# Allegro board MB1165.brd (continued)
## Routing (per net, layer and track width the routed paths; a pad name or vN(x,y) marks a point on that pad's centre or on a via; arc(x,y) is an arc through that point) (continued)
PAR_D4: length 149.9
  TOP w0.127: CN4.27 150.06,143.69 v1(150.47,143.28) ; U4.B13 83.61,132.89 87.08,132.89 87.5,132.46 87.5,131.57 89.53,129.54 93.09,129.54 94.57,128.06 94.57,124.12 95.76,122.94 CN6.53 111.12,122.94 111.46,123.27 v1(111.89,123.27)
  L3_SIG w0.102: v1(150.47,143.28) 150.47,143.94 151,144.47 151,145.29 150.68,145.62 149.61,145.62 148.99,146.23 148.99,156.55 147.22,158.32 126.29,158.32 125.48,159.13 103.76,159.13 102.88,158.25 102.35,158.25 101.07,156.97 98.04,156.97 v1(97.84,157.18)
  BOTTOM w0.127: R272.2 111.56,122.94 v1(111.89,123.27) 112.37,123.75 112.37,125.35 111.1,126.62 107.75,126.62 106.96,127.41 106.96,132.77 104.42,135.31 104.42,152.3 100.63,156.08 99.95,156.08 98.86,157.18 v1(97.84,157.18)
PAR_D5: length 92.8
  TOP w0.127: v1(150.5,142.42) 151.17,143.09 151.4,143.09 152,143.69 CN4.28 ; v1(111.86,143.26) 111.86,142.75 111.1,141.99 CN6.23 ; v5(82.81,134.49) U4.C11
  L3_SIG w0.102: v1(150.5,142.42) 148.69,142.42 145.41,145.69 145.41,152.98 143.21,155.19 135.13,155.19 129.67,149.73 120.9,149.73 113.94,142.77 113.27,142.77 112.78,143.26 v1(111.86,143.26) 110.74,143.26 108.69,141.2 98.2,141.2 92.38,135.38 88.16,135.38 87.15,136.4 86.06,136.4 84.68,135.03 83.35,135.03 v5(82.81,134.49)
PAR_D6: length 76.1
  TOP w0.127: CN4.29 148.75,142.69 147.45,143.99 147.45,146.61 147.19,146.86 v1(147.19,147.19) ; SB4.1 91.64,149.81 91.64,150.04 93.8,152.2 93.8,155.04 v1(93.85,155.09)
  L3_SIG w0.102: v1(147.19,147.19) 147.57,147.57 147.57,150.81 147,151.38 147,154.37 144.4,156.97 126.36,156.97 125.48,156.08 123.57,156.08 122.61,157.05 111.33,157.05 109.17,154.89 94.06,154.89 v1(93.85,155.09)
PAR_D7: length 58.6
  TOP w0.127: CN4.30 154.43,142.69 154.71,142.98 v1(155.63,142.98) ; SB17.1 v1(131.32,104.65)
  L3_SIG w0.102: v1(155.63,142.98) 155.93,142.67 155.93,121.89 150.9,116.87 146.69,116.87 143.13,113.31 141.33,113.31 136.22,108.2 133.96,108.2 131.32,105.56 v1(131.32,104.65)
PAR_D8: length 245.3
  TOP w0.127: R17.2 28.07,157.35 v1(29.72,157.35) ; U4.B14 83.64,132.06 86.45,132.06 89.35,129.16 92.71,129.16 94,127.87 94,123.82 96.16,121.67 CN6.55 111.07,121.67 111.58,122.17 v1(111.86,122.17) ; v1(150.62,153.01) 150.31,152.69 CN4.9
  L3_SIG w0.102: v1(29.72,157.35) 32.89,157.35 35.31,159.77 38.58,159.77 39.52,158.83 43.1,158.83 44.04,159.77 58.55,159.77 59.82,161.04 66.04,161.04 66.8,161.8 81.66,161.8 83.19,160.27 94.11,160.27 96.16,158.22 97.56,158.22 98.55,157.23 100.84,157.23 102.36,158.75 102.74,158.75 103.63,159.64 106.68,159.64 107.82,160.78 119,160.78 120.02,159.77 126.11,159.77 126.87,159 147.57,159 149.73,156.84 149.73,153.9 v1(150.62,153.01) 151.05,152.58 151.05,152.07 149.99,151 149.99,146.69 150.24,146.43 150.93,146.43 152.3,145.06 152.3,140.03 150.64,138.38 142.16,138.38 141.58,138.96 128.27,138.96 116.23,126.92 116.23,122.48 113.89,120.14 v1(113.89,118.24)
  BOTTOM w0.127: v1(113.89,118.24) 113.89,120.27 111.99,122.17 v1(111.86,122.17) 111.23,121.54 111.23,121.39 R278.2
PAR_D9: length 239.3
  TOP w0.127: v5(86.76,133.35) 86.74,133.35 86.36,133.73 84.37,133.73 U4.A12 ; CN17.5 v1(140.52,48.57) ; v1(154.94,152.69) CN4.10 ; CN6.28 113.61,139.45 v1(113.51,139.55)
  L3_SIG w0.102: v1(102.87,160.78) 106.43,160.78 107.31,161.67 126.62,161.67 127.81,160.48 147.75,160.48 149.48,158.75 150.75,158.75 152.15,157.35 152.15,156.08 154.47,153.76 154.47,153.17 v1(154.94,152.69) 155.96,151.68 155.96,149.39 156.24,149.11 156.24,121.59 151.08,116.43 146.69,116.43 143.21,112.95 141.43,112.95 139.95,111.48 139.95,102.87 142.24,100.58 142.24,50.29 v1(140.52,48.57) ; v5(86.76,133.35) 86.89,133.22 94.59,133.22 98.83,137.46 106.68,137.46 107.89,138.67 112.66,138.67 113.51,139.52 v1(113.51,139.55)
  BOTTOM w0.127: v1(113.51,139.55) 113.44,139.62 112.75,139.62 109.65,142.72 109.65,154.38 107.31,156.72 107.31,158.37 104.9,160.78 v1(102.87,160.78)
PAR_D10: length 115.8
  TOP w0.102: v5(83.61,134.49) 83.62,134.49 84.45,134.49 84.84,134.11 85.09,134.11
  TOP w0.127: v5(83.61,134.49) U4.B11 ; 85.09,134.11 86.61,134.11 87.88,132.84 87.88,131.7 89.66,129.92 93.47,129.92 98.93,124.46 JP6.2 101.5,126.77 v1(106.91,126.77) 109.97,126.77 CN6.47 ; v1(147.32,155.32) 147.95,154.69 CN4.5
  L3_SIG w0.102: v1(147.32,155.32) 145.34,157.3 125.93,157.3 125.22,156.59 124.08,156.59 123.32,157.35 111.12,157.35 108.99,155.22 100.86,155.22 v1(100.51,155.57)
  BOTTOM w0.127: v1(100.51,155.57) 100.69,155.57 104.06,152.2 104.06,135.2 106.71,132.56 106.71,126.97 v1(106.91,126.77)
PAR_D11: length 107.9
  TOP w0.127: v1(111.84,120.7) 111.53,120.4 CN6.57 96.49,120.4 93.47,123.42 93.47,127.64 92.33,128.78 89.15,128.78 86.36,131.57 v1(85.47,131.57) ; CN4.6 151.98,154.69 151.38,154.1 151.38,153.09 v1(150.62,152.32) ; v5(82.01,133.69) U4.D12
  L3_SIG w0.102: v1(85.47,131.57) 85.09,131.95 84.45,131.95 83.17,133.24 82.45,133.24 v5(82.01,133.69) ; v1(150.62,152.32) 149.73,151.43 149.73,146.43 149.99,146.18 150.83,146.18 152.02,144.98 152.02,140.72 151.51,140.21 146.49,140.21 145.67,139.4 128.14,139.4 115.77,127.03 115.77,122.68 113.94,120.85 112.01,120.85 111.86,120.7 v1(111.84,120.7)
  BOTTOM w0.127: SB83.2 111.56,120.4 111.56,120.42 v1(111.84,120.7)
PB0: length 37.2
  TOP w0.127: CN5.52 48.01,124.21 48.64,124.84 v1(48.77,124.84) 49.97,126.05 49.97,129.35 58.8,138.18 68.2,138.18 69.71,139.69 U4.R5
  BOTTOM w0.127: SB76.2 SB79.2 48.26,124.33 v1(48.77,124.84)
PB1: length 29.5
  TOP w0.127: U4.R4 68.35,140.49 67.44,139.57 65.91,139.57 64.77,140.72 v1(48.77,140.72) CN5.26
  BOTTOM w0.127: SB50.2 48.26,141.22 v1(48.77,140.72) ; SB51.2 47.62,140.97
PB2: length 81.9
  TOP w0.127: v1(43.43,138.3) 43.31,138.18 CN5.29 40.51,138.18 36.78,141.91 31.19,141.91 29.97,143.13 29.97,154.43 32.51,156.97 36.7,156.97 37.85,158.12 41.53,158.12 43.94,160.53 R6.2 ; U4.M5 v5(74.81,140.09)
  L3_SIG w0.102: v5(74.81,140.09) 74.81,139.83 74.42,139.45 74.42,139.2 74.16,138.93 73.95,138.93 73.53,138.51 73.53,138.05 72.26,136.78 71.12,136.78 70.42,136.08 67.75,136.08 66.67,135 56.64,135 54.48,137.16 49.78,137.16 49.28,137.67 44.2,137.67 43.56,138.3 v1(43.43,138.3)
PB3: length 31.7
  TOP w0.127: U4.A10 84.06,135.64 85.57,135.64 86.33,134.87 87.09,134.87 87.59,134.38 87.59,133.77 88.26,133.1 88.26,131.83 89.79,130.3 93.85,130.3 95.89,128.27 97.92,128.27 JP5.2 101.22,127.51 108.33,127.51 108.84,128.02 CN6.45
PB4: length 217.7
  TOP w0.102: 85.09,136.45 84.05,136.45 U4.A9
  TOP w0.127: v5(87.06,135.85) 86.47,136.45 85.09,136.45 ; v1(123.06,102.23) 123.19,102.11 124.84,102.11 R103.2 ; CN6.24 v1(113.54,141.99) ; v1(44.07,34.42) 44.07,34.29 43.68,33.9 U21.19
  L3_SIG w0.102: v1(44.07,34.42) 44.96,35.31 48.26,35.31 49.15,36.2 49.15,38.51 51.71,41.07 56.64,41.07 60.48,44.91 80.21,44.91 81.41,46.1 81.41,47.09 82.96,48.64 83.87,48.64 101.17,65.94 101.17,69.34 102.54,70.71 105.54,70.71 107.87,73.05 107.87,74.88 110.72,77.72 110.72,87.66 117.22,94.16 117.22,95.38 120.98,99.14 122.81,99.14 123.77,100.1 123.77,101.52 v1(123.06,102.23) ; v5(87.06,135.85) 87.08,135.85 87.93,135 92.58,135 98.4,140.82 108.94,140.82 110.74,142.62 112.9,142.62 v1(113.54,141.99) 125.09,141.99 v1(125.86,142.75)
  BOTTOM w0.127: v1(125.86,142.75) 126.62,141.99 126.62,116.46 121.67,111.51 121.67,103.63 v1(123.06,102.23)
PB5: length 55
  TOP w0.127: v1(44.7,153.03) 45.02,153.35 45.02,153.97 45.73,154.69 CN5.4 ; v5(84.56,137.21) 84.48,137.29 U4.A8
  L3_SIG w0.102: v5(84.56,137.21) 83.29,137.69 79.88,137.69 78.49,139.09 78.49,140.67 77.62,141.53 77.62,141.78 77.36,142.04 77.09,142.04 76.78,142.35 76.78,142.67 70.87,148.59 67.67,148.59 63.75,152.5 52.07,152.5 51.41,153.16 44.83,153.16 v1(44.7,153.03)
  BOTTOM w0.127: SB28.2 SB29.2 45.59,153.92 v1(44.7,153.03)
PB6: length 155
  TOP w0.127: v1(91.69,136.88) 91.34,136.53 R40.2 ; v1(33.66,151.51) U3.7 ; v1(113.54,145.8) CN6.18 116.59,145.8 119,148.21 119,158.62 v1(121.03,160.66)
  L3_SIG w0.102: v1(91.69,136.88) 98.48,143.66 108.1,143.66 110.87,146.43 112.9,146.43 v1(113.54,145.8)
  BOTTOM w0.127: v1(33.66,151.51) R215.2 35.43,152.02 35.43,158.24 39.88,162.69 39.88,168.28 42.27,170.66 111.02,170.66 v1(121.03,160.66)
PB7: length 94.9
  TOP w0.127: CN4.32 151.78,141.69 151.38,142.09 v1(151.05,142.09) ; v5(88.01,137.44) 87.99,137.44 87.22,138.2 87.22,139.09 86.49,139.83 84.43,139.83 84.2,140.06 83.58,140.06 U4.B5 ; CN6.21 111.05,143.26 111.56,143.76 112.27,143.76 112.67,144.17 v1(112.67,145.8)
  L3_SIG w0.102: v1(151.05,142.09) 151.05,142.54 150.75,142.85 148.87,142.85 145.75,145.97 145.75,153.21 143.26,155.7 135.13,155.7 129.67,150.24 119.89,150.24 114.81,145.16 113.54,145.16 112.9,145.8 v1(112.67,145.8) 111,145.8 108.41,143.21 98.63,143.21 92.56,137.13 91.82,136.4 89.71,136.4 89.1,137.01 88.44,137.01 v5(88.01,137.44)
PB8: length 452.5
  TOP w0.127: CN6.31 108.56,136.91 v1(107.77,136.12) 104.88,133.22 89.11,133.22 88.27,134.07 88.27,134.52 87.78,135 87.78,136.19 86.87,137.11 85.27,137.11 84.29,138.09 U4.A7 ; R5.1 40.64,161.54 v1(40.39,161.29) ; CN18.40 69.53,38.65 v1(69.47,38.59) 69.34,38.46 R151.2 ; CN15.44 100.32,80.38 99.44,79.5 99.44,78.11 100.46,77.09 100.46,75.18 101.22,74.42 101.22,70.05 v1(102.34,68.94) ; v1(125.09,23.34) 124.69,23.34 R179.1
  L3_SIG w0.102: v1(40.39,161.29) 40.89,161.8 62.06,161.8 62.3,161.56 62.66,161.56 62.9,161.8 66.17,161.8 66.55,162.18 81.92,162.18 83.44,160.66 94.36,160.66 96.39,158.62 97.66,158.62 98.81,157.48 100.46,157.48 102.49,159.51 v1(102.74,159.51) 103,159.51 103.5,160.02 106.3,160.02 107.57,161.29 126.24,161.29 127.64,159.89 147.83,159.89 150.62,157.1 150.62,155.7 151.05,155.27 v1(151.05,154.46) 152.91,152.6 152.91,149.48 154.36,148.03 154.36,145.72 153.77,145.14 153.77,135.92 155.57,134.11 155.57,122.12 150.75,117.3 146.56,117.3 142.93,113.67 141.22,113.67 136.14,108.58 133.91,108.58 130.78,105.46 130.78,101.45 126.75,97.41 125.86,97.41 117.4,88.95 117.4,79.4 112.33,74.33 112.33,71.06 111.06,69.79 109.69,69.79 v1(109.37,69.47) 79.27,39.37 70.25,39.37 v1(69.47,38.59) 64.5,38.59 63.67,37.76 56.94,37.76 54.99,35.81 v1(54.99,35.69)
  BOTTOM w0.127: v1(102.74,159.51) 103.76,159.51 105.03,158.24 105.03,156.97 107.75,154.25 107.75,136.14 v1(107.77,136.12) ; v1(102.34,68.94) 108.84,68.94 v1(109.37,69.47) ; v1(69.47,38.59) 74.79,33.27 101.6,33.27 111.51,23.37 125.07,23.37 v1(125.09,23.34) ; v1(151.05,154.46) 151.38,154.46 151.74,154.81 T5.3 152.53,154.35 R295.1 ; R287.1 55.5,35.18 v1(54.99,35.69)
PB9: length 539
  TOP w0.127: v1(102.34,69.7) 101.73,70.31 101.73,74.68 100.84,75.56 100.84,77.47 99.95,78.36 99.95,79.25 101.32,80.62 CN15.40 ; v1(113.54,148.34) CN6.14 116.97,148.34 118.49,149.86 118.49,158.88 v1(120.27,160.66) ; CN18.38 v1(70.8,38.61) 70.8,37.71 R152.2 ; R4.1 v1(40.64,167.39) ; R172.1 127.51,26.67 v1(125.98,26.67) ; U4.B4 83.61,140.89 84.79,140.89 85.23,140.45 86.25,140.45 v5(86.49,140.68)
  L3_SIG w0.102: v1(102.34,69.7) 102.84,70.21 105.66,70.21 108.18,72.72 108.18,74.7 111.05,77.57 111.05,87.48 117.6,94.03 117.6,95.33 120.88,98.6 122.71,98.6 125.91,101.8 127.25,101.8 127.51,102.06 127.51,103.33 126.03,104.8 126.03,110.82 126.72,111.51 130.91,111.51 131.44,112.04 131.44,112.93 133.6,115.09 138.66,115.09 140.34,116.76 141.96,116.76 145.47,120.27 149.71,120.27 150.19,120.75 150.19,127.56 150.98,128.35 152.83,128.35 153.75,129.26 153.75,133.63 152.58,134.8 152.58,145.41 151.31,146.69 150.62,146.69 150.24,147.07 150.24,150.88 151.51,152.15 151.51,153.03 150.55,154 v1(150.55,154.91) 150.24,155.22 150.24,156.84 147.7,159.38 127.13,159.38 126.36,160.15 120.78,160.15 v1(120.27,160.66) ; v1(113.54,148.34) 112.9,148.97 110.74,148.97 109.22,147.45 95.76,147.45 92.2,143.89 90.83,143.89 89.28,142.34 88.14,142.34 v5(86.49,140.68) ; v1(118.31,73.71) 118.31,70.54 115.52,67.74 115.52,37.85 116.1,37.26 116.1,33.43 118.41,31.11 118.41,30.71 118.24,30.53 118.24,29.79 119.05,28.98 122.12,28.98 124.43,26.67 v1(125.98,26.67) ; v1(70.8,38.61) 70.17,37.97 64.52,37.97 64.01,37.47 57.38,37.47 v1(55.63,35.71)
  BOTTOM w0.127: v1(120.27,160.66) 110.74,170.18 43.43,170.18 v1(40.64,167.39) ; R288.1 56.13,34.04 56.13,35.18 55.63,35.69 v1(55.63,35.71) ; v1(118.31,73.71) 119.05,74.45 119.05,84.53 117.47,86.11 117.47,96.39 116.84,97.03 116.84,111.73 123.7,118.59 123.7,130.81 122.92,131.58 122.92,138.44 117.08,144.28 117.08,145.02 113.77,148.34 v1(113.54,148.34) ; v1(150.55,154.91) 150.32,154.69 T6.3 148.12,152.36 R296.1 ; v1(70.8,38.61) 71.81,38.61 76.63,33.78 101.98,33.78 111.89,23.88 122.1,23.88 124.89,26.67 v1(125.98,26.67)
PB10: length 110.2
  TOP w0.127: v1(43.36,135.56) 43.28,135.64 CN5.33 ; R94.2 v1(34.8,107.57) ; v5(73.21,133.69) U4.P12
  L3_SIG w0.102: v1(34.8,107.57) 34.8,107.65 39.22,112.06 39.22,125.65 38.73,126.14 38.73,129.84 38.86,129.97 39.9,129.97 40.03,130.1 40.03,132.54 40.16,132.66 42.37,132.66 42.47,132.76 42.47,132.97 42.37,133.07 39.39,133.07 39.27,133.19 39.27,133.36 39.39,133.47 42.37,133.47 42.47,133.58 42.47,133.78 42.37,133.88 39.45,133.88 39.32,134.01 39.32,134.21 39.45,134.34 42.29,134.34 42.42,134.47 42.42,134.62 42.29,134.74 39.4,134.74 39.27,134.87 39.27,135.02 39.4,135.15 42.34,135.15 42.47,135.28 42.47,135.43 42.34,135.56 39.34,135.56 39.22,135.68 39.22,135.88 39.34,136 42.37,136 42.49,136.13 42.49,136.28 42.37,136.41 39.34,136.41 39.22,136.54 39.22,136.69 39.34,136.82 42.34,136.82 42.47,136.94 42.47,137.1 42.34,137.22 39.34,137.22 39.22,137.35 39.22,137.54 39.34,137.67 42.47,137.67 43,137.13 43,135.92 v1(43.36,135.56) 48.18,135.56 48.59,135.15 53.77,135.15 55.83,133.1 67.16,133.1 68.35,134.29 72.64,134.29 73.21,133.72 v5(73.21,133.69)
PB11: length 110
  TOP w0.127: v1(44.25,135.03) 45.09,135.03 45.75,134.37 CN5.36 ; v1(34.8,106.17) 35.43,105.54 R98.2 ; v5(72.41,132.89) U4.R13
  L3_SIG w0.102: v1(34.8,106.17) 34.8,105.46 34.92,105.33 35.18,105.33 35.31,105.46 35.31,107.64 39.57,111.91 39.57,126.31 39.09,126.8 39.09,129.57 39.22,129.69 40.28,129.69 40.41,129.82 40.41,131.29 40.51,131.4 43.06,131.4 43.18,131.52 43.18,131.68 43.06,131.8 40.51,131.8 40.41,131.9 40.41,132.16 40.54,132.28 42.57,132.28 42.75,132.46 42.75,134.85 42.93,135.03 v1(44.25,135.03) 44.37,135.15 45.7,135.15 45.82,135.03 45.82,134.49 45.93,134.37 46.1,134.37 46.22,134.49 46.22,135.06 46.34,135.18 46.51,135.18 46.63,135.06 46.63,134.51 46.75,134.39 46.92,134.39 47.03,134.51 47.03,135.03 47.15,135.15 47.32,135.15 47.44,135.03 47.44,134.51 47.56,134.39 47.73,134.39 47.85,134.51 47.85,134.96 47.97,135.08 48.13,135.08 48.25,134.96 48.25,134.49 48.37,134.37 48.54,134.37 48.66,134.49 48.66,134.65 48.76,134.75 48.96,134.75 49.07,134.65 49.07,134.13 49.19,134.01 49.35,134.01 49.47,134.13 49.47,134.65 49.57,134.75 49.78,134.75 49.88,134.65 49.88,133.39 50,133.27 50.17,133.27 50.29,133.39 50.29,134.65 50.39,134.75 50.59,134.75 50.69,134.65 50.69,132.76 50.81,132.64 50.98,132.64 51.1,132.76 51.1,134.65 51.2,134.75 51.4,134.75 51.5,134.65 51.5,132.64 51.63,132.51 51.84,132.51 51.97,132.64 51.97,134.62 52.1,134.75 52.3,134.75 52.43,134.62 52.43,132.56 52.55,132.44 52.79,132.44 52.92,132.56 52.92,134.57 53.05,134.7 53.26,134.7 53.39,134.57 53.39,132.41 53.52,132.28 68.12,132.28 68.25,132.41 68.25,133.73 68.38,133.86 68.61,133.86 68.71,133.76 68.71,132.72 68.81,132.61 69.01,132.61 69.11,132.72 69.11,133.76 69.22,133.86 69.42,133.86 69.52,133.76 69.52,132.72 69.62,132.61 69.82,132.61 69.93,132.72 69.93,133.76 70.03,133.86 70.23,133.86 70.33,133.76 70.33,132.72 70.43,132.61 70.64,132.61 70.74,132.72 70.74,133.76 70.84,133.86 71.04,133.86 71.15,133.76 71.15,132.72 71.25,132.61 71.45,132.61 71.55,132.72 71.55,133.76 71.65,133.86 72.28,133.86 72.41,133.73 v5(72.41,132.89)
PB12: length 48.6
  TOP w0.127: U4.L13 76.38,132.92 v5(76.43,132.92) ; CN5.41 43.15,130.56 v1(43.41,130.3)
  L3_SIG w0.102: v5(76.43,132.92) 76.38,132.92 74.87,131.41 74.87,129.86 71.25,126.24 65.34,126.24 62.5,129.08 49.07,129.08 48.36,129.79 44.83,129.79 44.32,130.3 v1(43.41,130.3)
  BOTTOM w0.127: R254.2 44.96,127.51 44.45,128.02 44.45,129.67 44.07,130.05 43.66,130.05 v1(43.41,130.3) 43.28,130.43 SB70.2 SB74.2
PB13: length 110.5
  TOP w0.127: v1(43.56,128.27) 42.55,129.29 CN5.43 ; U4.K14 76.41,132.09 v5(76.34,132.09) ; R109.2 v1(34.67,102.87)
  L3_SIG w0.102: v1(34.67,102.87) 34.67,103.12 34.8,103.25 36.07,103.25 36.2,103.38 36.2,107.34 40.41,111.56 40.41,116.71 40.54,116.84 42.09,116.84 42.24,116.99 42.24,124.66 42.82,125.25 42.82,126.64 42.72,126.75 41.38,126.75 41.25,126.87 41.25,127.08 41.38,127.2 43,127.2 43.13,127.33 43.13,127.51 43,127.64 41.39,127.64 41.27,127.75 41.27,127.92 41.39,128.04 42.83,128.04 42.95,128.16 42.95,128.33 42.83,128.45 41.35,128.45 41.25,128.55 41.25,128.75 41.35,128.85 42.67,128.85 42.77,128.96 42.77,129.16 42.67,129.26 41.38,129.26 41.25,129.39 41.25,129.59 41.38,129.72 43.28,129.72 43.41,129.59 43.41,128.42 v1(43.56,128.27) 43.81,128.27 43.92,128.37 43.92,129.44 44.04,129.57 44.22,129.57 44.35,129.44 44.35,127.61 44.5,127.46 45.65,127.46 45.77,127.58 45.77,128.74 45.89,128.85 46.06,128.85 46.18,128.74 46.18,126.79 46.3,126.67 46.47,126.67 46.59,126.79 46.59,128.74 46.7,128.85 46.87,128.85 46.99,128.74 46.99,126.76 47.11,126.64 47.28,126.64 47.4,126.76 47.4,128.71 47.52,128.83 47.69,128.83 47.8,128.71 47.8,126.74 47.92,126.62 48.09,126.62 48.21,126.74 48.21,128.68 48.34,128.8 48.56,128.8 48.69,128.68 48.69,126.77 48.82,126.64 49.02,126.64 49.15,126.77 49.15,127.97 49.28,128.09 49.5,128.09 49.63,127.97 49.63,126.77 49.76,126.64 63.86,126.64 65.02,125.48 71.5,125.48 75.39,129.37 75.39,131.14 v5(76.34,132.09)
  BOTTOM w0.127: R255.2 42.8,127.51 v1(43.56,128.27)
PB14: length 38.9
  TOP w0.127: CN5.35 43.56,134.37 43.79,134.14 v1(43.79,133.91) ; v5(72.41,132.09) U4.R14
  L3_SIG w0.13: v1(43.79,133.91) 43.79,134.09 44.15,134.44 44.94,134.44 46.26,133.12 49.12,133.12 50.67,131.57 69.39,131.57 69.7,131.88 72.2,131.88 v5(72.41,132.09)
  BOTTOM w0.127: SB65.2 SB64.2
  BOTTOM w0.155: v1(43.79,133.91) 43.79,134.11 43.28,134.62 41.02,134.62 40.89,134.49 40.89,134.11
PB15: length 38.7
  TOP w0.127: v1(44.45,133.91) 45.26,133.1 CN5.38 ; v5(72.41,131.29) U4.R15
  L3_SIG w0.13: v1(44.45,133.91) 44.45,133.93 44.58,134.06 44.78,134.06 46.1,132.74 48.97,132.74 50.52,131.19 69.55,131.19 69.86,131.5 72.2,131.5 v5(72.41,131.29)
  BOTTOM w0.127: SB61.2 SB62.2
  BOTTOM w0.155: v1(44.45,133.91) 44.45,133.99 43.43,135 41.02,135 40.89,135.13 40.89,135.51
PC0: length 56.4
  TOP w0.127: v1(36.32,141.22) 35.84,140.74 32.66,140.74 JP3.3 ; v5(74.81,142.49) U4.M2 ; CN5.11 42.55,149.61 43.05,150.11 v1(43.43,150.11)
  L3_SIG w0.102: v1(36.32,141.22) 36.5,141.4 36.5,143.81 39.75,147.07 39.75,148.87 41,150.11 v1(43.43,150.11) 44.09,150.11 44.88,149.33 50.52,149.33 51.83,148.02 56.43,148.02 57.81,146.63 63.42,146.63 64.52,145.54 66.8,145.54 67.59,144.75 68.86,144.75 69.42,144.2 72.82,144.2 73.65,143.36 73.65,143.14 73.92,142.88 74.42,142.88 v5(74.81,142.49)
  BOTTOM w0.127: v1(43.43,150.11) 42.93,150.62 SB34.1
PC1: length 43.3
  TOP w0.127: v1(44.7,151.89) 43.94,151.13 43.94,147.96 v1(44.83,147.07) CN5.16 ; U4.M3 v5(74.81,141.69)
  L3_SIG w0.102: v1(44.83,147.07) 45.34,147.07 46.15,146.25 49.45,146.25 51.74,143.97 59.74,143.97 60.71,143 64.64,143 65.53,142.11 74.38,142.11 v5(74.81,141.69)
  BOTTOM w0.127: SB41.1 45.34,147.57 v1(44.83,147.07) ; v1(44.7,151.89) 45.09,152.27 SB31.1
PC2: length 41.6
  TOP w0.127: CN5.23 v1(43.41,141.99) ; U4.M4 v5(74.81,140.89)
  L3_SIG w0.102: v5(74.81,140.89) 74.39,140.46 73.15,140.46 72.19,139.5 70.66,139.5 69.34,138.18 58.8,138.18 56.39,140.59 49.91,140.59 48.95,141.55 43.84,141.55 v1(43.41,141.99)
  BOTTOM w0.127: v1(43.41,141.99) 43.28,142.11 41.4,142.11 SB49.1 R233.1
PC3: length 42
  TOP w0.127: v1(44.32,139.32) 44.2,139.45 CN5.27 ; U4.L4 v5(75.61,140.89)
  L3_SIG w0.102: v5(75.61,140.89) 75.61,140.89 75.18,140.46 74.68,140.46 74.42,140.21 74.42,139.95 74.17,139.7 73.92,139.7 73.65,139.43 73.65,139.19 71.88,137.41 70.87,137.41 70.1,136.65 67.18,136.65 66.42,135.89 58.33,135.89 55.92,138.3 45.85,138.3 44.83,139.32 v1(44.32,139.32)
  BOTTOM w0.127: v1(44.32,139.32) 44.32,139.06 44.7,138.68 45.59,138.68 45.85,138.43 ; 46.1,136.78 SB54.1
PC4: length 41.4
  TOP w0.127: v5(74.01,140.09) U4.N5 ; v1(43.18,140.08) 42.55,140.72 CN5.25
  L3_SIG w0.102: v1(43.18,140.08) 45.34,140.08 45.97,139.45 56.13,139.45 58.67,136.91 66.17,136.91 66.55,137.29 69.72,137.29 71.25,138.81 72.39,138.81 72.85,139.28 72.85,139.43 73.15,139.73 73.65,139.73 v5(74.01,140.09)
  BOTTOM w0.127: SB53.1 39.75,138.3 41.15,138.3 41.91,139.06 SB52.1 v1(43.18,140.08)
PC5: length 36.9
  TOP w0.102: U4.P5 73.19,140.11 71.63,140.11
  TOP w0.127: v1(44.96,128.52) 45.21,128.52 45.72,128.02 CN5.46 47.96,128.02 58.5,138.56 67.94,138.56 69.49,140.11 71.63,140.11
  BOTTOM w0.127: v1(44.96,128.52) 45.59,128.52 SB73.1 SB69.1
PC13: length 209.4
  TOP w0.127: v1(121.16,82.14) 118.52,79.5 108.71,79.5 106.68,77.47 106.68,54.43 102.16,49.91 102.16,36.02 97.21,31.06 89.74,31.06 88.27,29.59 88.27,19.43 R203.2 ; U4.D1 v5(82.01,143.29) ; CN6.6 114.3,153.42 113.46,152.58 v1(113.46,152.53)
  L3_SIG w0.102: v5(82.01,143.29) 82.01,144.34 85.75,148.08 90.17,148.08 91.44,149.35 92.96,149.35 96.16,152.55 109.75,152.55 110.41,151.89 112.62,151.89 113.26,152.53 v1(113.46,152.53)
  BOTTOM w0.127: v1(121.16,82.14) 121.16,86.36 119.89,87.63 119.89,98.42 120.14,98.68 120.14,112.5 125.27,117.63 125.27,132.08 124.59,132.77 124.59,139.7 119.14,145.15 119.14,146.57 113.46,152.25 v1(113.46,152.53)
PC14: length 9.4
  TOP w0.203: R19.2 84.12,148.39 v1(83.44,147.7) 83.31,147.57 82.68,147.57 82.3,147.19 82.3,146.05 80.64,144.4 80.64,143.05 U4.E1
  BOTTOM w0.127: SB35.1 83.95,148.46 83.44,147.96 v1(83.44,147.7)
PC15: length 8.8
  TOP w0.203: U4.F1 80.14,143.01 80.14,144.65 81.66,146.18 81.66,147.07 v1(80.98,147.75) 80.31,148.41 R18.2
  BOTTOM w0.127: v1(80.98,147.75) 80.9,147.75 80.26,148.39 SB36.1
PD4: length 134.1
  TOP w0.102: v4(72.9,105.37) 73.03,105.37 73.57,105.92 75.36,105.92 U9.G2 ; v5(68.71,76.07) 68.33,75.7 68.33,75.12 U16.A2
  TOP w0.127: CN11.28 v3(103.38,100.89) ; v5(82.01,134.49) U4.D11
  L3_SIG w0.102: v3(103.38,100.89) 102.67,101.6 93.45,101.6 93.07,101.98 92.23,101.98 92.13,101.87 92.13,100.94 92.03,100.84 91.83,100.84 91.73,100.94 91.73,101.87 91.63,101.98 82.16,101.98 81.58,101.4 80.09,101.4 77.8,103.68 77.8,104.03 77.57,104.26 77.06,104.78 73.49,104.78 v4(72.9,105.37)
  BOTTOM w0.127: v5(82.01,134.49) 82.05,134.49 82.42,134.11 83.82,134.11 87.88,130.05 87.88,113.41 100.97,100.33 102.82,100.33 v3(103.38,100.89) ; v4(72.9,105.37) 73.46,105.37 73.58,105.5 73.58,105.79 73.46,105.92 73.03,105.92 72.9,106.05 72.9,106.27 73.03,106.4 73.56,106.4 73.69,106.53 73.69,106.76 73.56,106.88 72.54,106.88 72.42,106.76 72.42,105.5 72.29,105.37 71.99,105.37 71.86,105.5 71.86,105.84 71.73,105.97 71.48,105.97 71.35,105.84 71.35,105.5 71.22,105.37 70.92,105.37 65.84,100.28 65.84,83.67 67.06,82.45 67.06,78.62 67.18,78.5 67.72,78.5 67.84,78.37 67.84,78.12 67.72,77.99 67.18,77.99 67.06,77.86 67.06,77.57 67.18,77.44 68.53,77.44 68.66,77.31 68.66,77.06 68.53,76.93 67.18,76.93 67.06,76.8 67.06,76.61 67.18,76.48 68.58,76.48 68.71,76.35 v5(68.71,76.07)
PD5: length 65.6
  TOP w0.127: v5(82.81,135.29) U4.C10 ; R99.2 v3(90.04,103.5) ; CN11.26 v3(103.38,102.16)
  L3_SIG w0.102: v3(90.04,103.5) 96.28,103.5 96.38,103.4 96.38,102.87 96.48,102.77 96.69,102.77 96.79,102.87 96.79,103.4 96.89,103.5 97.09,103.5 97.2,103.4 97.2,102.87 97.3,102.77 97.5,102.77 97.6,102.87 97.6,103.4 97.7,103.5 98.42,103.5 99.06,102.87 103.28,102.87 103.38,102.77 v3(103.38,102.16)
  BOTTOM w0.127: v3(103.38,102.16) 102.79,101.57 101.24,101.57 88.65,114.17 88.65,130.43 87.63,131.44 87.63,132.59 87.32,132.89 86.05,132.89 85.66,133.29 85.66,133.67 84.2,135.13 82.97,135.13 v5(82.81,135.29)
PD7: length 75
  TOP w0.127: v3(78.49,109.47) 78.61,109.6 R85.2 ; v5(87.2,134.21) 87.02,134.21 86.74,134.49 84.96,134.49 84.57,134.89 U4.A11 ; CN11.24 v3(103.38,103.43)
  L3_SIG w0.102: v3(78.49,109.47) 78.11,109.09 78.11,108.2 80.14,106.17 82.3,106.17 84.02,104.44 98.63,104.44 99.06,104.01 102.79,104.01 v3(103.38,103.43)
  BOTTOM w0.127: v5(87.2,134.21) 87.4,134.21 89.47,132.14 89.47,125.67 90.04,125.09 90.04,114.17 101.35,102.87 102.82,102.87 v3(103.38,103.43)
PE0: length 146.2
  TOP w0.102: v5(71.25,71.5) 71.25,74.55 70.26,75.54 U16.A1 ; v5(89.46,70.43) U15.K9
  TOP w0.127: v5(86,138.43) 86,138.46 85.78,138.68 84.71,138.68 84.51,138.89 U4.A6 ; CN11.25 v3(101.98,102.16)
  L3_SIG w0.102: v5(89.46,70.43) 89.46,69.62 89.59,69.49 90.02,69.49 90.14,69.62 90.14,70.89 90.02,71.02 88.82,71.02 88.7,71.15 88.7,71.6 88.57,71.72 88.17,71.72 87.81,72.08 87.81,72.32 87.61,72.52 84.91,72.52 84.7,72.32 84.7,72.13 84.18,71.6 81.13,71.6 v1(80.77,71.25) 76.71,71.25 76.45,71.5 v5(71.25,71.5)
  BOTTOM w0.127: v5(86,138.43) 86.16,138.43 86.36,138.23 86.36,136.4 86.59,136.17 86.59,134.26 88.07,132.78 88.07,131.57 89.09,130.56 89.09,125.29 89.66,124.71 89.66,113.92 101.42,102.16 v3(101.98,102.16) 102.67,102.16 103.25,102.74 103.73,102.74 104.32,102.16 104.32,93.27 102.87,91.82 88.19,91.82 87.38,91.01 87.38,85.5 84.89,83.01 84.89,78.56 85.43,78.02 85.43,76.32 85.43,75.53 85.22,75.32 84.94,75.32 84.81,75.19 84.81,74.93 84.94,74.81 85.55,74.81 85.67,74.68 85.67,74.47 85.55,74.35 84.43,74.35 84.3,74.22 84.3,73.94 84.43,73.81 85.55,73.81 85.67,73.69 85.67,73.43 85.55,73.3 84.56,73.3 84.43,73.18 84.43,71.42 84.31,71.3 84.05,71.3 83.93,71.42 83.93,73.18 83.8,73.3 83.54,73.3 83.42,73.18 83.42,71.42 83.29,71.3 83.04,71.3 82.91,71.42 82.91,73.18 82.78,73.3 82.55,73.3 82.42,73.18 82.42,71.37 82.3,71.25 82.04,71.25 81.92,71.37 81.92,72.42 81.79,72.54 81.54,72.54 81.41,72.42 81.41,71.37 81.28,71.25 v1(80.77,71.25)
PE1: length 153.7
  TOP w0.102: v5(89.46,77.93) U15.K1 ; 67.94,78.23 67.56,77.85 67.56,75.14 U16.B2
  TOP w0.127: CN11.23 v3(101.98,103.43) ; U4.A5 84.19,139.69 84.43,139.45 86.28,139.45 86.79,138.94 86.79,138.18 v5(86.82,138.15) ; v5(68.83,79.12) 67.94,78.23
  L3_SIG w0.102: v5(68.83,79.12) 68.91,79.2 85.17,79.2 v1(85.34,79.38) 85.34,79.35 85.47,79.22 86.46,79.22 86.59,79.1 86.59,78.64 86.69,78.54 86.89,78.54 86.99,78.64 86.99,79.27 87.12,79.4 87.33,79.4 87.45,79.27 87.45,77.52 87.58,77.39 88.11,77.39 88.24,77.52 88.24,79.38 88.37,79.5 89.44,79.5 89.56,79.38 89.56,79.21 89.44,79.1 88.7,79.1 88.57,78.97 88.57,78.79 88.7,78.66 89.46,78.66 89.59,78.54 89.59,78.44 89.46,78.31 89.15,78.31 89.03,78.18 89.03,77.8 88.9,77.67 88.69,77.67 88.57,77.55 88.57,77.39 88.69,77.27 88.98,77.27 89.1,77.15 89.1,76.98 88.98,76.86 88.77,76.86 88.65,76.73 88.65,76.58 88.77,76.45 88.9,76.45 89.03,76.33 89.03,76.17 88.9,76.05 88.67,76.05 88.54,75.92 88.54,75.79 88.67,75.67 89.33,75.67 89.46,75.79 v5(89.46,77.93)
  BOTTOM w0.127: v1(85.34,79.38) 85.34,82.85 85.47,82.97 90.07,82.97 90.2,83.1 90.2,83.35 90.07,83.48 86.61,83.48 86.49,83.61 86.49,83.86 86.61,83.99 90.07,83.99 90.2,84.12 90.2,84.37 90.07,84.5 88.01,84.5 87.88,84.62 87.88,90.86 88.47,91.44 103.25,91.44 104.72,92.91 104.72,96.07 104.85,96.2 105.28,96.2 105.41,96.32 105.41,96.58 105.28,96.7 104.85,96.7 104.72,96.83 104.72,97.08 104.85,97.21 105.28,97.21 105.41,97.34 105.41,97.59 105.28,97.72 104.85,97.72 104.72,97.85 104.72,98.1 104.85,98.23 105.28,98.23 105.41,98.35 105.41,98.61 105.28,98.74 104.85,98.74 104.72,98.86 104.72,99.12 104.85,99.24 105.28,99.24 105.41,99.37 105.41,99.62 105.28,99.75 104.85,99.75 104.72,99.88 104.72,100.13 104.85,100.26 105.28,100.26 105.41,100.39 105.41,100.64 105.28,100.77 104.85,100.77 104.72,100.89 104.72,101.15 104.85,101.28 105.28,101.28 105.41,101.4 105.41,101.66 105.28,101.78 104.85,101.78 104.72,101.91 104.72,102.16 104.85,102.29 105.28,102.29 105.41,102.42 105.41,102.67 105.28,102.8 104.85,102.8 104.72,102.93 104.72,103.38 104.09,104.01 103.12,104.01 102.54,103.43 v3(101.98,103.43) 101.74,103.43 101.46,103.71 101.21,103.71 90.42,114.49 90.42,125.48 89.92,125.98 89.92,132.33 87.55,134.7 87.55,135.97 86.74,136.78 86.74,138.07 v5(86.82,138.15)
PF6: length 51.5
  TOP w0.127: v1(43.31,151.96) 43.29,151.96 43.1,152.15 CN5.7 37.21,152.15 37.08,152.02 37.08,143.38 36.96,143.26 31.62,143.26 31.5,143.38 31.5,146.23 30.78,146.94 v1(30.73,146.94) ; R25.2 65.66,147.83 v1(65.28,148.21)
  L3_SIG w0.102: v1(65.28,148.21) 64.77,148.72 64.77,150.24 63.5,151.51 48.77,151.51 47.73,152.55 44.53,152.55 43.93,151.96 v1(43.31,151.96)
  BOTTOM w0.127: R227.2 31.11,146.56 v1(30.73,146.94)
PF7: length 52.3
  TOP w0.127: v1(65.28,148.97) 65.41,148.84 R23.2 ; v1(30.73,151) 32.51,151 32.64,151.13 32.64,151.51 32.51,151.64 31.37,151.64 31.24,151.76 31.24,152.53 32.51,153.8 34.8,153.8 38.35,157.35 48.26,157.35 50.42,155.19 50.42,152.78 v1(49.91,152.27) 49.78,152.15 CN5.8
  L3_SIG w0.102: v1(65.28,148.97) 65.28,150.37 63.63,152.02 50.16,152.02 v1(49.91,152.27)
  BOTTOM w0.127: v1(30.73,151) 30.48,151.26 R217.1
PF8: length 52.2
  TOP w0.127: v1(43.41,145.8) CN5.17 38.99,145.8 38.61,146.18 38.61,149.4 38.48,149.53 37.72,149.53 37.59,149.4 37.59,143 37.47,142.88 30.86,142.88 30.73,143 v1(30.73,146.05)
  L3_SIG w0.102: v1(43.41,145.8) 44.04,145.16 45.09,145.16 45.59,144.65 48.64,144.65 50.93,142.37 56.9,142.37 58.04,141.22 62.36,141.22 63.63,139.95 64.77,139.95 v1(65.15,139.57)
  BOTTOM w0.127: v1(65.15,139.57) 65.66,139.06 R237.2 ; R228.1 30.23,146.56 v1(30.73,146.05)
PF9: length 52
  TOP w0.127: CN5.12 48.72,149.61 v1(49.3,150.19) 50.93,151.82 50.93,155.32 48.51,157.73 38.2,157.73 34.64,154.18 32.13,154.18 30.73,152.78 v1(30.73,151.76) ; R27.2 v1(65.28,146.81)
  L3_SIG w0.102: v1(65.28,146.81) 64.77,146.81 63.86,147.73 59.92,147.73 57.45,150.19 v1(49.3,150.19)
  BOTTOM w0.127: R216.2 31.24,151.26 v1(30.73,151.76)
PF10: length 59.9
  TOP w0.127: v1(34.92,139.83) 34.59,139.5 26.62,139.5 25.91,140.21 25.91,143.67 U3.16 ; CN5.9 v1(43.43,150.88)
  L3_SIG w0.102: v1(34.92,139.83) 34.92,144.4 35.74,145.21 35.74,146.74 39.37,150.37 39.88,150.37 40.39,150.88 v1(43.43,150.88) 43.99,151.43 45.19,151.43 45.49,151.13 57.66,151.13 60.33,148.46 64.14,148.46 64.9,147.7 67.94,147.7 v1(68.33,148.08)
  BOTTOM w0.127: R222.2 68.71,148.46 v1(68.33,148.08)
PF11: length 114.2
  TOP w0.102: 90.26,70.09 U15.J9
  TOP w0.127: v1(90.81,66.22) 90.81,67.72 90.26,68.26 90.26,70.09 ; CN10.8 55.68,113.59 55.24,113.16 v3(54.74,113.16) ; R48.2 v1(64.52,124.59)
  L3_SIG w0.102: v3(54.74,113.16) 54.36,113.16 53.85,113.67 53.14,113.67 51.31,111.84 51.31,79.78 66.47,64.62 89.03,64.62 90.63,66.22 v1(90.81,66.22)
  BOTTOM w0.127: v1(64.52,124.59) 64.06,124.13 64.06,119.74 63.73,119.4 63.55,119.4 63.36,119.59 63.18,119.59 63,119.41 63,119.23 63.19,119.04 63.19,118.86 63.01,118.68 62.83,118.68 62.64,118.87 62.46,118.87 62.28,118.69 62.28,118.51 62.47,118.32 62.47,118.14 62.29,117.96 62.11,117.96 61.92,118.15 61.74,118.15 61.56,117.97 61.56,117.79 61.75,117.61 61.75,117.43 61.57,117.25 61.39,117.25 61.2,117.43 61.02,117.43 60.84,117.25 60.84,117.07 61.03,116.89 61.03,116.71 60.85,116.53 60.67,116.53 60.48,116.72 60.3,116.72 60.12,116.54 60.12,116.36 60.31,116.17 60.31,115.99 60.13,115.81 59.95,115.81 59.76,116 59.58,116 59.4,115.82 59.4,115.64 59.59,115.45 59.59,115.27 59.41,115.09 59.23,115.09 59.04,115.28 58.86,115.28 58.68,115.1 58.68,114.92 58.87,114.73 58.87,114.55 58.69,114.37 58.51,114.37 58.33,114.56 58.15,114.56 57.97,114.38 57.97,114.2 58.15,114.01 58.15,113.83 57.48,113.16 v3(54.74,113.16)
PG7: length 203.9
  TOP w0.127: CN5.47 v1(43.41,126.75) ; U4.J14 77.24,132.12 77.24,130.17 75.94,128.86 v3(75.94,128.63) ; U23.D3 v2(117.61,28.33)
  L3_SIG w0.102: v1(43.41,126.75) 43.92,126.24 49.4,126.24 50.16,125.48 61.98,125.48 64.01,123.44 73.53,123.44 74.3,124.21 74.3,126.99 v3(75.94,128.63)
  BOTTOM w0.127: v1(43.41,126.75) 41.83,125.17 41.83,113.08 47.32,107.59 47.32,91.08 55.6,82.81 55.6,71.87 64.74,62.73 64.74,53.75 66.8,51.69 71.25,51.69 72.14,50.8 72.14,48.64 71.37,47.88 71.37,44.32 72.52,43.18 72.52,41.4 75.18,38.73 75.18,36.2 77.09,34.29 102.74,34.29 112.75,24.28 117.07,24.28 117.61,24.82 v2(117.61,28.33)
PG8: length 124.2
  TOP w0.102: v5(90.68,77.79) U15.J1
  TOP w0.127: v3(54.99,92.38) 54.99,92.5 55.76,93.27 CN10.40
  L3_SIG w0.102: v3(54.99,92.38) 55.22,92.38 55.35,92.25 55.35,91.95 55.42,91.87 55.7,91.87 55.78,91.95 55.78,92.25 55.91,92.38 56.1,92.38 56.2,92.27 56.2,91.91 56.32,91.8 56.49,91.8 56.6,91.91 56.6,92.27 56.71,92.38 56.91,92.38 57.01,92.27 57.01,92.02 57.11,91.92 57.32,91.92 57.42,92.02 57.42,92.27 57.52,92.38 57.72,92.38 57.82,92.27 57.82,92.02 57.93,91.92 58.13,91.92 58.23,92.02 58.23,92.27 58.33,92.38 58.54,92.38 58.64,92.27 58.64,92.02 58.74,91.92 58.94,91.92 59.04,92.02 59.04,92.27 59.14,92.38 59.35,92.38 59.45,92.27 59.45,92.02 59.55,91.92 59.75,91.92 59.86,92.02 59.86,92.27 59.96,92.38 60.16,92.38 60.26,92.27 60.26,92.02 60.36,91.92 60.57,91.92 60.67,92.02 60.67,92.27 60.77,92.38 60.97,92.38 61.08,92.27 61.08,92.02 61.18,91.92 61.38,91.92 61.48,92.02 61.48,92.27 61.58,92.38 61.79,92.38 61.89,92.27 61.89,92.02 61.99,91.92 62.19,91.92 62.29,92.02 62.29,92.27 62.4,92.38 62.6,92.38 62.7,92.27 62.7,92.02 62.8,91.92 63.01,91.92 63.11,92.02 63.11,92.27 63.21,92.38 63.41,92.38 63.51,92.27 63.51,92.02 63.62,91.92 63.82,91.92 63.92,92.02 63.92,92.27 64.02,92.38 64.22,92.38 64.33,92.27 64.33,92.02 64.43,91.92 64.63,91.92 64.73,92.02 64.73,92.27 64.83,92.38 65.04,92.38 65.14,92.27 65.14,92.02 65.24,91.92 65.44,91.92 65.55,92.02 65.55,92.27 65.65,92.38 65.85,92.38 65.95,92.27 65.95,92.02 66.05,91.92 66.26,91.92 66.36,92.02 66.36,92.27 66.46,92.38 66.66,92.38 66.76,92.27 66.76,92.02 66.87,91.92 67.07,91.92 67.17,92.02 67.17,92.27 67.27,92.38 67.48,92.38 67.58,92.27 67.58,92.02 67.68,91.92 67.88,91.92 67.98,92.02 67.98,92.27 68.09,92.38 68.29,92.38 68.39,92.27 68.39,92.02 68.49,91.92 68.7,91.92 68.8,92.02 68.8,92.27 68.9,92.38 69.1,92.38 69.2,92.27 69.2,92.02 69.3,91.92 69.51,91.92 69.61,92.02 69.61,92.27 69.71,92.38 69.91,92.38 70.02,92.27 70.02,92.02 70.12,91.92 70.32,91.92 70.42,92.02 70.42,92.26 70.54,92.38 70.71,92.38 70.83,92.26 70.83,92.02 70.93,91.92 71.13,91.92 71.24,92.02 71.24,92.27 71.34,92.38 71.54,92.38 71.64,92.27 71.64,92.02 71.74,91.92 71.95,91.92 72.05,92.02 72.05,92.27 72.15,92.38 72.35,92.38 72.45,92.27 72.45,92.02 72.56,91.92 72.76,91.92 72.86,92.02 72.86,92.27 72.96,92.38 73.17,92.38 73.27,92.27 73.27,92.02 73.37,91.92 73.57,91.92 73.67,92.02 73.67,92.27 73.78,92.38 73.98,92.38 74.08,92.27 74.08,92.02 74.18,91.92 74.38,91.92 74.49,92.02 74.49,92.27 74.59,92.38 74.79,92.38 74.89,92.27 74.89,92.02 74.99,91.92 75.2,91.92 75.3,92.02 75.3,92.27 75.4,92.38 75.6,92.38 75.71,92.27 75.71,92.02 75.81,91.92 76.01,91.92 76.11,92.02 76.11,92.27 76.21,92.38 76.42,92.38 76.52,92.27 76.52,92.02 76.62,91.92 76.82,91.92 76.92,92.02 76.92,92.27 77.03,92.38 77.23,92.38 77.33,92.27 77.33,92.02 77.43,91.92 77.64,91.92 77.74,92.02 77.74,92.27 77.84,92.38 78.04,92.38 78.14,92.27 78.14,92.02 78.25,91.92 78.45,91.92 78.55,92.02 78.55,92.27 78.65,92.38 78.86,92.38 78.96,92.27 78.96,92.02 79.06,91.92 79.26,91.92 79.36,92.02 79.36,92.27 79.46,92.38 79.67,92.38 79.77,92.27 79.77,92.02 79.87,91.92 80.07,91.92 80.18,92.02 80.18,92.27 80.28,92.38 80.48,92.38 80.58,92.27 80.58,92.02 80.68,91.92 80.89,91.92 80.99,92.02 80.99,92.27 81.09,92.38 81.29,92.38 81.4,92.27 81.4,92.02 81.5,91.92 81.7,91.92 81.8,92.02 81.8,92.27 81.9,92.38 82.11,92.38 82.21,92.27 82.21,92.02 82.31,91.92 82.51,91.92 82.61,92.02 82.61,92.27 82.72,92.38 82.92,92.38 83.02,92.27 83.02,92.02 83.12,91.92 83.33,91.92 83.43,92.02 83.43,92.27 83.53,92.38 83.73,92.38 83.83,92.27 83.83,92.02 83.94,91.92 84.14,91.92 84.24,92.02 84.24,92.27 84.34,92.38 84.54,92.38 84.65,92.27 84.65,92.02 84.75,91.92 84.95,91.92 85.05,92.02 85.05,92.27 85.15,92.38 85.36,92.38 85.46,92.27 85.46,92.02 85.56,91.92 85.76,91.92 85.87,92.02 85.87,92.27 85.97,92.38 86.17,92.38 86.27,92.27 86.27,92.02 86.37,91.92 86.58,91.92 86.68,92.02 86.68,92.27 86.78,92.38 86.98,92.38 87.08,92.27 87.08,82.55 87.21,82.42 90.55,82.42 90.68,82.3 v5(90.68,77.79)
  BOTTOM w0.127: v3(54.99,92.38) 56.09,93.47 56.13,93.47 56.77,94.11 57.11,94.11 76.03,113.03 77.22,113.03 77.47,113.28 77.47,120.8 77.72,121.05 77.72,121.06 78.02,121.35 79.48,121.35 79.6,121.48 79.6,125.2 R267.2
PG9: length 122.2
  TOP w0.127: CN11.27 v1(101.98,100.89) ; v5(82.01,136.09) U4.D9 ; R135.2 70.36,63.37 v1(70.33,63.35)
  L3_SIG w0.102: v1(70.33,63.35) 90.53,63.35 94.01,66.83 95.35,66.83 96.01,67.48 96.01,67.63 95.67,67.97 95.67,68.11 95.81,68.25 95.96,68.25 96.3,67.92 96.44,67.92 96.58,68.06 96.58,68.2 96.08,68.71 96.08,68.88 96.2,68.99 96.37,68.99 96.87,68.49 97.01,68.49 97.16,68.63 97.16,68.78 96.65,69.28 96.65,69.45 96.77,69.57 96.94,69.57 97.45,69.07 97.59,69.07 97.73,69.21 97.73,69.35 97.23,69.86 97.23,70.03 97.35,70.14 97.52,70.14 98.02,69.64 98.16,69.64 98.37,69.85 98.37,76.4 99.01,77.04 99.01,81.28 100.08,82.35 100.08,86.41 105,91.34 105,100.13 104.88,100.25 102.11,100.25 101.98,100.38 v1(101.98,100.89)
  BOTTOM w0.127: v1(101.98,100.89) 101.17,100.89 88.25,113.8 88.25,130.24 85.09,133.41 85.09,133.6 83.82,134.87 82.63,134.87 82.42,135.08 82.42,135.67 v5(82.01,136.09)
PG11: length 37.1
  TOP w0.127: U4.B8 83.59,136.91 84.23,136.91 84.3,136.83 86.66,136.83 87.48,136.02 87.48,134.9 87.88,134.49 87.88,133.99 89.28,132.59 105.16,132.59 108.2,135.64 CN6.33 111.99,135.64 v1(112.12,135.76)
  BOTTOM w0.127: R242.1 112.24,135.89 v1(112.12,135.76) SB60.1
PG13: length 29.6
  TOP w0.127: CN6.25 108.84,140.72 106.69,142.86 94.32,142.86 SB8.1 92.81,142.01 91.95,142.88 90.17,142.88 R36.1 89.28,142.49 83.82,142.49 83.58,142.25 83.58,141.66 U4.B3
PG14: length 33.4
  TOP w0.127: v1(111.99,139.62) 111.99,139.01 111.15,138.18 CN6.29 108.08,138.18 106.17,136.27 93.09,136.27 91.95,137.41 91.31,137.41 91.06,137.16 89.2,137.16 87.97,138.39 87.97,138.85 86.63,140.2 84.72,140.2 84.43,140.49 U4.A4
  BOTTOM w0.127: v1(111.99,139.62) 111.4,140.21 R235.1
PG15: length 121.8
  TOP w0.102: v5(89.06,72.17) U15.K7
  TOP w0.127: R41.2 91.82,133.99 v3(92.08,133.73) ; CN11.19 v3(101.98,105.97)
  BOTTOM w0.127: v3(92.08,133.73) 92.08,115.39 101.5,105.97 v3(101.98,105.97) 102.67,105.97 103.25,106.55 104.52,106.55 105.79,105.28 105.79,95.85 105.66,95.72 105.26,95.72 105.13,95.59 105.13,95.34 105.26,95.21 105.66,95.21 105.79,95.08 105.79,94.83 105.66,94.7 105.26,94.7 105.13,94.58 105.13,94.32 105.26,94.19 105.66,94.19 105.79,94.07 105.79,93.81 105.66,93.69 105.26,93.69 105.13,93.56 105.13,93.24 105.26,93.11 105.64,93.11 105.77,92.99 105.77,92.73 105.64,92.61 105.05,92.61 103.35,90.91 88.49,90.91 88.37,90.78 88.37,90.45 88.49,90.32 90.68,90.32 90.81,90.2 90.81,89.82 90.68,89.69 88.39,89.69 88.27,89.57 88.27,89.31 88.39,89.19 90.68,89.19 90.81,89.06 90.81,88.8 90.68,88.68 88.39,88.68 88.27,88.55 88.27,88.3 88.39,88.17 90.68,88.17 90.81,88.04 90.81,87.79 90.68,87.66 88.39,87.66 88.27,87.53 88.27,87.28 88.39,87.15 90.68,87.15 90.81,87.03 90.81,86.77 90.68,86.65 88.39,86.65 88.27,86.52 88.27,86.26 88.39,86.14 90.68,86.14 90.81,86.01 90.81,85.76 90.68,85.63 88.39,85.63 88.27,85.5 88.27,85.25 88.39,85.12 90.68,85.12 90.81,84.99 90.81,81.61 90.68,81.48 89.48,81.48 89.36,81.36 89.36,81.03 89.48,80.9 90.11,80.9 90.23,80.77 90.23,78.68 89.92,78.36 89.92,77.6 89.41,77.09 89.41,72.52 v5(89.06,72.17)
PH0: length 8
  TOP w0.203: U4.G1 78.87,143.23 78.87,147.32 v1(78.11,148.08) 77.09,149.1 R20.1
  BOTTOM w0.203: v1(78.11,148.08) 77.72,148.08 77.47,148.34
PH1: length 16.2
  TOP w0.203: U4.H1 78.46,142.94 78.46,145.69 76.58,147.57 75.44,147.57 v1(74.8,148.21) C23.1 73.15,149.86 73.15,153.67 X1.1
  BOTTOM w0.127: 73.78,148.89 74.12,148.89 v1(74.8,148.21)
PH2: length 128.6
  TOP w0.127: v5(76.41,140.89) U4.K4 ; v3(103.38,118.11) 103.63,118.11 104.34,117.4 CN11.2
  BOTTOM w0.127: R285.2 91.31,90.2 91.44,90.32 91.71,90.32 91.84,90.2 91.84,89.31 91.97,89.18 92.22,89.18 92.35,89.31 92.35,90.2 92.48,90.32 92.73,90.32 92.86,90.2 92.86,89.31 92.98,89.18 93.24,89.18 93.37,89.31 93.37,90.2 93.49,90.32 93.75,90.32 93.87,90.2 93.87,89.31 94,89.18 94.25,89.18 94.38,89.31 94.38,90.2 94.51,90.32 94.76,90.32 94.89,90.2 94.89,89.31 95.02,89.18 95.27,89.18 95.4,89.31 95.4,90.2 95.52,90.32 95.78,90.32 95.91,90.2 95.91,89.31 96.03,89.18 96.29,89.18 96.41,89.31 96.41,90.2 96.54,90.32 96.79,90.32 96.92,90.2 96.92,89.31 97.05,89.18 97.3,89.18 97.43,89.31 97.43,90.2 97.56,90.32 97.81,90.32 97.94,90.2 97.94,89.31 98.06,89.18 98.32,89.18 98.45,89.31 98.45,90.2 98.57,90.32 104.04,90.32 106.17,92.46 106.17,111.76 104.58,113.35 104.58,116.9 v3(103.38,118.11) 103.12,118.36 103.12,130.25 99.44,133.93 99.44,141.92 98.81,142.56 98.81,145.54 95.12,149.22 89.41,149.22 88.33,148.15 84.95,148.15 83.41,146.61 78.18,146.61 76.71,145.14 76.71,143.79 75.98,141.96 75.98,141.84 75.98,141.52 76.41,141.09 v5(76.41,140.89)
PH3: length 118.5
  TOP w0.102: 89.92,70.09 89.9,70.1 89.9,71.41 U15.J8
  TOP w0.127: v1(90.75,64.92) 89.92,67.49 89.92,70.09 ; v3(53.21,118.26) 52.35,117.4 CN10.1
  L3_SIG w0.102: v1(90.75,64.92) 89.51,63.68 86.79,63.68 86.56,63.91 66.12,63.91 50.67,79.35 50.67,112.09 v3(53.21,118.26)
  BOTTOM w0.127: R243.1 65.91,135.38 65.15,134.62 63.14,134.62 59.82,131.29 v3(53.21,118.26)
PH4: length 49
  TOP w0.127: v1(43.48,136.91) 44.2,137.62 44.2,138.38 44.58,138.76 45.03,138.76 45.72,139.45 CN5.28 ; U4.H4 v5(78.01,140.09)
  L3_SIG w0.102: v5(78.01,140.09) 77.62,139.7 77.62,138.4 77.01,137.79 76.61,137.79 76.11,137.29 73.79,137.29 72.9,136.4 71.37,136.4 70.61,135.64 68.02,135.64 66.75,134.37 56.52,134.37 54.23,136.65 43.74,136.65 v1(43.48,136.91)
  BOTTOM w0.127: v1(43.48,136.91) 43.23,136.65 41.4,136.65 SB56.1 SB57.1
PH5: length 112.3
  TOP w0.102: U15.K8 89.1,71.41 89.1,70.09
  TOP w0.127: 89.1,70.09 89.1,69.04 87.93,67.87 87.93,64.54 87.58,64.19 v5(87.58,64.16) ; CN10.2 55.58,117.4 v3(54.86,118.11)
  L3_SIG w0.102: v5(87.58,64.16) 87.48,64.26 66.27,64.26 51,79.53 51,112.09 53.07,117.23 53.95,118.11 v3(54.86,118.11)
  BOTTOM w0.127: v3(54.86,118.11) 61.76,132.68 63.2,134.11 R246.1
PH6: length 176.1
  TOP w0.127: v1(124.59,141.05) 124.59,156.59 v1(125.35,157.35) ; v1(44.07,131.44) 43.61,131.9 43.61,132.03 42.55,133.1 CN5.37 ; v5(73.21,132.89) U4.P13
  L3_SIG w0.102: v1(124.59,141.05) 124.36,140.82 120.07,140.82 116.41,137.16 v1(113.41,137.16) ; v1(44.07,131.44) 44.53,131.9 45.44,131.9 46.18,131.17 48.46,131.17 49.4,130.23 63.69,130.23 66.02,127.89 71.5,127.89 73.41,129.79 73.41,132.69 v5(73.21,132.89) ; v1(125.35,157.35) 124.92,156.92 124.26,156.92 123.55,157.63 110.9,157.63 108.89,155.63 104.5,155.63 v1(103.99,156.13)
  BOTTOM w0.127: v1(44.07,131.44) 44.07,131.32 44.45,130.94 44.96,130.94 45.34,131.32 46.86,131.32 49.89,134.34 49.89,138.66 54.66,143.43 54.66,149.07 60.2,154.61 63.25,154.61 67.19,158.55 69.06,158.55 69.22,158.7 73.79,158.7 74.19,159.11 74.75,159.11 75.41,158.45 80.24,158.45 80.7,158.9 93.07,158.9 93.51,159.35 101.76,159.35 103.25,157.86 103.25,156.87 v1(103.99,156.13) ; SB55.1 114.53,137.16 v1(113.41,137.16) 112.94,137.63 112.15,137.63 111.84,137.31 110.82,137.31
PH7: length 166.1
  TOP w0.127: R42.2 124.08,130.68 124.08,156.84 v1(124.59,157.35) ; CN5.40 45.09,131.83 v1(44.7,131.44) ; v5(74.01,132.89) U4.N13
  L3_SIG w0.102: v1(44.7,131.44) 45.21,131.44 45.92,130.73 48.51,130.73 49.4,129.84 63.53,129.84 65.87,127.51 71.81,127.51 74.01,129.71 v5(74.01,132.89) ; v1(104.9,156.08) 108.66,156.08 110.49,157.91 124.03,157.91 v1(124.59,157.35)
  BOTTOM w0.127: v1(104.9,156.08) 104.78,156.08 103.66,157.2 103.66,157.96 101.94,159.68 93.39,159.68 92.86,159.16 80.57,159.16 80.21,158.8 75.56,158.8 75,159.36 73.81,159.36 73.51,159.05 69.19,159.05 68.97,158.84 66.92,158.84 63.05,154.97 59.99,154.97 54.31,149.28 54.31,143.55 49.53,138.77 49.53,135.2 46.02,131.7 44.96,131.7 v1(44.7,131.44)
PI4: length 130
  TOP w0.102: 93.09,70.09 93.09,71.34 U15.F8
  TOP w0.127: v1(93.98,65.41) 93.34,66.04 93.34,69.83 93.09,70.09 ; v5(82.81,141.69) U4.C3 ; CN11.17 v3(101.98,107.24)
  L3_SIG w0.102: v1(93.98,65.41) 94.49,65.41 99.75,70.66 99.75,74.83 99.87,74.96 100.59,74.96 100.69,74.85 100.69,74.04 100.79,73.94 101,73.94 101.1,74.04 101.1,74.85 101.2,74.96 101.4,74.96 101.51,74.85 101.51,74.04 101.61,73.94 101.81,73.94 101.91,74.04 101.91,74.85 102.01,74.96 102.22,74.96 102.32,74.85 102.32,74.04 102.42,73.94 102.62,73.94 102.72,74.04 102.72,74.85 102.83,74.96 103.03,74.96 103.13,74.85 103.13,74.04 103.23,73.94 103.44,73.94 103.54,74.04 103.54,74.85 103.64,74.96 103.84,74.96 103.94,74.85 103.94,74.04 104.05,73.94 104.25,73.94 104.35,74.04 104.35,74.85 104.45,74.96 104.65,74.96 104.76,74.85 104.76,74.04 104.86,73.94 105.06,73.94 105.16,74.04 105.16,74.85 105.26,74.96 105.47,74.96 105.57,74.85 105.57,74.04 105.67,73.94 105.87,73.94 105.98,74.04 105.98,74.85 106.08,74.96 106.2,74.96 106.32,74.83 106.32,74.07 106.45,73.94 106.65,73.94 106.78,74.07 106.78,75.29 106.68,75.39 106.22,75.39 106.12,75.49 106.12,75.7 106.22,75.8 106.68,75.8 106.78,75.9 106.78,76.1 106.68,76.2 106.22,76.2 106.12,76.31 106.12,76.51 106.22,76.61 106.68,76.61 106.78,76.71 106.78,83.06 107.52,83.79 107.52,88.27 106.78,89 106.78,105.79 104.85,107.72 102.46,107.72 v3(101.98,107.24)
  BOTTOM w0.127: v3(101.98,107.24) 101.68,107.24 93.75,115.16 93.75,118.9 93.62,119.02 93.09,119.02 92.96,119.15 92.96,136.65 92.2,137.41 91.19,137.41 91.06,137.54 89.66,137.54 88.77,138.43 88.77,139.01 86.72,141.07 86.72,142.09 86.14,142.67 84.5,142.67 83.52,141.69 v5(82.81,141.69)
PI5: length 130.2
  TOP w0.102: U15.F2 93.09,76.14 93.09,75.56 94.87,73.79 97.73,73.79
  TOP w0.127: v5(82.01,141.69) U4.D3 ; 97.73,73.79 99.31,73.79 99.69,74.17 v1(100.2,74.17) ; CN11.15 v3(101.98,108.51)
  L3_SIG w0.102: v1(100.2,74.17) 100.13,74.09 100.13,72.39 100.25,72.26 100.46,72.26 100.58,72.39 100.58,73.51 100.71,73.63 100.89,73.63 101.02,73.51 101.02,72.38 101.14,72.26 101.31,72.26 101.43,72.38 101.43,73.53 101.53,73.63 101.73,73.63 101.83,73.53 101.83,72.38 101.95,72.26 102.12,72.26 102.24,72.38 102.24,73.53 102.34,73.63 102.55,73.63 102.65,73.53 102.65,72.38 102.77,72.26 102.93,72.26 103.05,72.38 103.05,73.53 103.16,73.63 103.36,73.63 103.46,73.53 103.46,72.38 103.58,72.26 103.75,72.26 103.87,72.38 103.87,73.53 103.97,73.63 104.17,73.63 104.27,73.53 104.27,72.38 104.39,72.26 104.56,72.26 104.68,72.38 104.68,73.53 104.78,73.63 104.98,73.63 105.09,73.53 105.09,72.38 105.2,72.26 105.37,72.26 105.49,72.38 105.49,73.53 105.59,73.63 106.91,73.63 107.16,73.89 107.16,82.7 107.92,83.46 107.92,88.32 107.16,89.08 107.16,103.07 107.26,103.17 107.9,103.17 108,103.28 108,103.48 107.9,103.58 107.26,103.58 107.16,103.68 107.16,103.89 107.26,103.99 107.9,103.99 108,104.09 108,104.29 107.9,104.39 107.26,104.39 107.16,104.5 107.16,104.7 107.26,104.8 107.9,104.8 108,104.9 108,105.11 107.9,105.21 107.26,105.21 107.16,105.31 107.16,105.51 107.26,105.61 107.9,105.61 108,105.71 108,105.92 107.9,106.02 107.26,106.02 105.26,108.03 102.08,108.03 101.98,108.13 v3(101.98,108.51)
  BOTTOM w0.127: v5(82.01,141.69) 82.41,142.09 83.34,142.09 84.3,143.05 86.42,143.05 87.1,142.37 87.1,141.27 89.15,139.22 89.15,138.81 89.51,138.46 92.68,138.46 93.73,137.41 93.73,119.94 93.85,119.81 94.56,119.81 94.69,119.68 94.69,115.67 101.85,108.51 v3(101.98,108.51)
PI8: length 225.6
  TOP w0.127: U4.C2 v5(82.81,142.49) ; CN6.9 111.15,150.88 111.73,151.46 v1(111.89,151.46)
  L3_SIG w0.102: v5(82.81,142.49) 82.81,144.53 85.85,147.57 90.3,147.57 91.57,148.84 93.09,148.84 96.47,152.22 109.55,152.22 110.26,151.51 111.84,151.51 v1(111.89,151.46) 112.73,151.46 113.21,151.94 127.23,151.94 v1(128.27,152.98) ; v1(57.05,35.28) 57.53,35.76 69.42,35.76 72.64,38.99 79.45,38.99 108.92,68.45 110.31,68.45 112.65,70.79 112.65,74.22 117.7,79.27 117.7,88.82 123.42,94.54 125.37,94.54 126.31,95.48 126.31,96.47 131.83,101.98 131.83,105.28 134.11,107.57 v1(134.37,107.57)
  BOTTOM w0.127: R290.1 56.52,33.15 56.52,34.75 v1(57.05,35.28) ; v1(128.27,152.98) 128.37,152.98 131.65,149.71 131.65,129.72 136.73,124.64 136.73,120.9 134.21,118.39 134.21,107.72 v1(134.37,107.57)
PI11: length 52.5
  TOP w0.127: CN5.2 45.57,155.96 45.19,155.57 45.19,154.86 44.09,153.77 v1(44.09,153.42) ; U4.F3 v5(80.41,141.69)
  L3_SIG w0.102: v1(44.09,153.42) 44.22,153.54 64.26,153.54 66.42,151.38 69.52,151.38 73.46,147.45 75.87,147.45 77.11,146.2 77.11,143.97 77.6,143.48 78.18,143.48 79.12,142.54 79.12,141.45 79.27,141.3 79.76,141.3 80.14,141.69 v5(80.41,141.69)
  BOTTOM w0.127: v1(44.09,153.42) 43.71,153.03 42.67,153.03 SB30.1 SB32.1
PI12: length 198.6
  TOP w0.127: U4.E3 v5(81.21,141.69) ; CN18.26 78.42,37.67 v1(79.39,36.7) ; CN6.7 111.1,152.15 111.28,152.32 v1(111.89,152.32)
  L3_SIG w0.102: v1(111.89,152.32) 110.49,152.32 109.96,152.86 93.55,152.86 89.28,148.59 85.72,148.59 81.65,144.52 81.65,142.13 v5(81.21,141.69)
  BOTTOM w0.127: v1(79.39,36.7) 80.02,36.07 96.77,36.07 99.95,39.24 99.95,51.65 121.92,73.62 121.92,86.49 120.27,88.14 120.27,98.17 120.52,98.42 120.52,112.24 125.58,117.3 125.58,136.04 125.12,136.5 125.12,141.25 114.31,152.07 114.31,152.56 113.86,153.01 113.28,153.01 112.6,152.32 v1(111.89,152.32)
PI13: length 209.3
  TOP w0.127: v1(117.65,152.81) 117.65,154.86 116.56,155.96 CN6.2 ; U4.G3 v5(79.61,141.69) ; v1(78.61,36.58) 78.54,36.58 77.15,37.96 CN18.28
  L3_SIG w0.102: v5(79.61,141.69) 79.61,141.75 80.04,142.18 80.04,144.04 80.9,144.91 80.9,145.8 85.09,149.99 88.39,149.99 91.97,153.57 110.49,153.57 110.69,153.37 113.95,153.37 114.51,152.81 v1(117.65,152.81)
  BOTTOM w0.127: v1(117.65,152.81) 117.65,149.91 126.21,141.35 126.21,116.79 121.28,111.86 121.28,98.04 120.97,97.72 120.97,88.84 123.06,86.74 123.06,73.49 101.35,51.77 101.35,39.12 97.03,34.8 80.39,34.8 v1(78.61,36.58)
PI14: length 155.4
  TOP w0.127: CN18.32 74.61,38.56 v1(74.42,38.37) ; v1(52.07,137.67) 49.53,137.67 v1(49.02,137.16) 48.77,136.91 CN5.32
  BOTTOM w0.127: R214.1 60.96,152.27 56.82,148.13 56.82,142.67 52.07,137.92 v1(52.07,137.67) ; v1(74.42,38.37) 71.63,41.16 71.63,42.8 69.85,44.58 69.85,47.75 70.74,48.64 70.74,49.4 69.98,50.16 65.53,50.16 63.14,52.56 63.14,62.04 54.07,71.11 54.07,81.93 45.8,90.21 45.8,106.86 40.54,112.12 40.54,124.22 37.85,126.92 37.85,131.06 39.12,132.33 43.6,132.33 43.86,132.59 45.21,132.59 48.9,136.27 48.9,137.03 v1(49.02,137.16)
PK7: length 221.4
  TOP w0.127: CN15.57 96.82,86.02 96.65,85.85 93.34,85.85 92.96,85.47 92.96,84.07 93.22,83.82 96.52,83.82 96.9,83.44 111.38,83.44 111.63,83.19 R125.1 119.43,83.19 v1(120.7,84.45) ; U4.C4 v5(82.81,140.89) ; v1(113.39,151.49) 113.39,151.64 113.89,152.15 CN6.8 ; v1(82.55,36.7) R153.2
  L3_SIG w0.102: v1(113.39,151.49) 113.23,151.49 112.78,151.03 110.01,151.03 108.33,149.35 94.74,149.35 93.47,148.08 91.95,148.08 90.23,146.37 89.6,146.37 87.25,144.02 86.29,144.02 83.16,140.89 v5(82.81,140.89)
  BOTTOM w0.127: v1(82.55,36.7) 95.5,36.7 99.44,40.64 99.44,51.85 120.7,73.11 v1(120.7,84.45) 120.7,86.11 119.43,87.38 119.43,96.7 118.08,98.04 118.08,110.92 124.92,117.75 124.92,131.83 124.3,132.45 124.3,139.45 118.71,145.03 118.71,146.27 113.49,151.49 v1(113.39,151.49)
